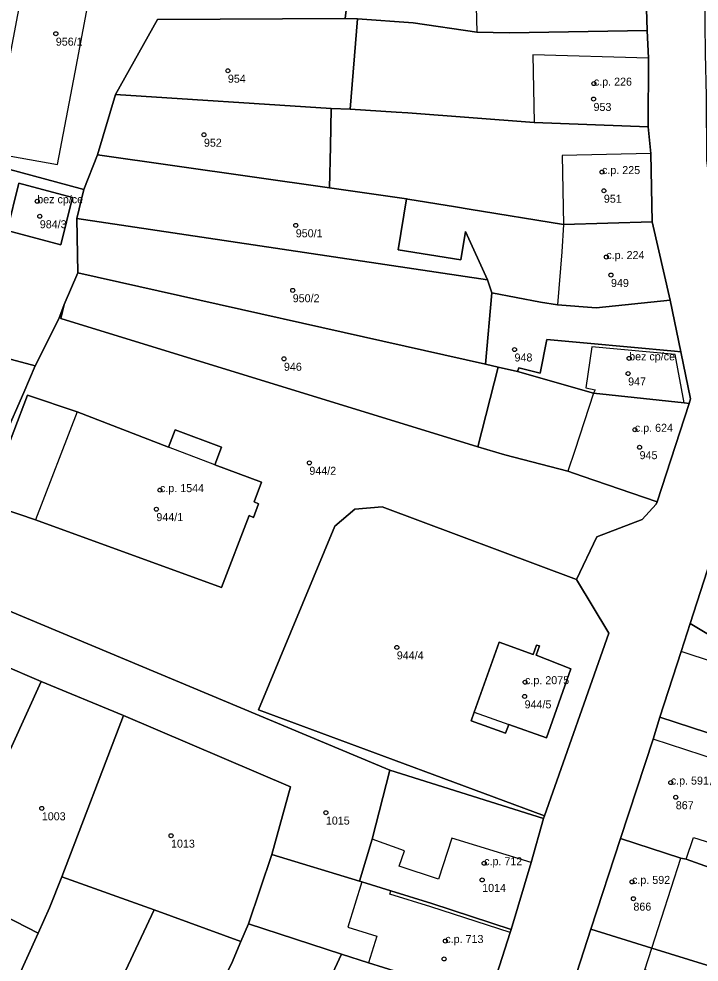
# Model space of a CAD drawing. Extents: x -878211 to -870363, y -1058464 to -1052522.
# Drawn here: x -874902.9 to -874817.9, y -1056517.4 to -1056399.5 of the extents above; entities that cross this region are included whole.
import ezdxf

# ---------------------------------------------------------------- set-up
doc = ezdxf.new("R2010")
doc.units = 0
for name, color, linetype in [('Vrstva 50', 7, 'Continuous'), ('Vrstva 51', 7, 'Continuous'), ('Vrstva 52', 7, 'Continuous')]:
    doc.layers.add(name, color=color, linetype=linetype)

msp = doc.modelspace()

# ---------------------------------------------------------------- linework, layer by layer
at = {"layer": 'Vrstva 50'}
for centre in [(-874898.26, -1056401.36994), (-874876.77, -1056405.99994), (-874831.06, -1056407.60994), (-874831.1, -1056409.52994), (-874879.76, -1056413.99994), (-874830.04, -1056418.65994), (-874829.81, -1056420.99994), (-874900.58, -1056422.30994), (-874900.26, -1056424.18994), (-874868.29, -1056425.31994), (-874829.5, -1056429.27994), (-874828.92, -1056431.52994), (-874868.67, -1056433.43994), (-874840.97, -1056440.83994), (-874869.77, -1056441.99994), (-874826.65, -1056441.93994), (-874826.78, -1056443.83994), (-874825.94, -1056450.86994), (-874825.35, -1056453.04994), (-874866.59, -1056454.99994), (-874885.25, -1056458.40994), (-874885.7, -1056460.78994), (-874855.67, -1056478.06994), (-874839.65, -1056482.40994), (-874839.71, -1056484.18994), (-874821.45, -1056494.95994), (-874820.83, -1056496.79994), (-874900.01, -1056498.17994), (-874864.53, -1056498.71994), (-874883.87, -1056501.59994), (-874844.76, -1056505.03994), (-874845.01, -1056507.12994), (-874826.29, -1056507.36994), (-874826.12, -1056509.46994), (-874849.61, -1056514.75994), (-874849.76, -1056516.99994)]:
    msp.add_circle(centre, 0.25, dxfattribs=at)
at = {"layer": 'Vrstva 51'}
for points in [[(-874923.91, -1056412.98), (-874894.75, -1056420.85), (-874893.04, -1056416.51), (-874890.82, -1056408.96), (-874885.57, -1056399.58), (-874862.13, -1056399.47), (-874861.41, -1056393.71), (-874850.27, -1056392.72), (-874850.58, -1056385.39), (-874853.91, -1056385.5), (-874889.34, -1056382.25), (-874889.5, -1056381.99), (-874894.83, -1056381.48), (-874894.82, -1056381.67), (-874905.74, -1056380.82), (-874918.12, -1056382.02), (-874920.55, -1056383.05), (-874924.5, -1056401.21)], [(-874862.13, -1056399.47), (-874860.57, -1056399.52), (-874853.61, -1056399.99), (-874845.68, -1056401.18), (-874841.61, -1056401.26), (-874824.39, -1056400.97), (-874824.63, -1056394.12), (-874824.76, -1056391.85), (-874850.27, -1056392.72), (-874861.41, -1056393.71)], [(-874862.13, -1056399.47), (-874885.57, -1056399.58), (-874890.82, -1056408.96), (-874863.85, -1056410.72), (-874861.51, -1056410.81), (-874860.57, -1056399.52)], [(-874824.39, -1056400.97), (-874841.61, -1056401.26), (-874845.68, -1056401.18), (-874853.61, -1056399.99), (-874860.57, -1056399.52), (-874861.51, -1056410.81), (-874855.77, -1056411.19), (-874854.3, -1056411.26), (-874838.5, -1056412.46), (-874824.27, -1056413.02), (-874824.24, -1056404.41)], [(-874863.85, -1056410.72), (-874890.82, -1056408.96), (-874893.04, -1056416.51), (-874864.08, -1056420.64), (-874863.96, -1056415.48)], [(-874855.77, -1056411.19), (-874861.51, -1056410.81), (-874863.85, -1056410.72), (-874863.96, -1056415.48), (-874864.08, -1056420.64), (-874854.48, -1056422.01), (-874854.28, -1056422.04), (-874848.36, -1056423.02), (-874846.63, -1056423.3), (-874834.84, -1056425.2), (-874823.79, -1056424.87), (-874823.94, -1056416.32), (-874824.27, -1056413.02), (-874838.5, -1056412.46), (-874854.3, -1056411.26)], [(-874900.82, -1056442.88), (-874897.87, -1056436.98), (-874897.22, -1056435.2), (-874895.51, -1056431.25), (-874895.62, -1056424.45), (-874894.75, -1056420.85), (-874923.91, -1056412.98), (-874927.21, -1056413.07), (-874929.49, -1056422.89), (-874932.5, -1056434.41)], [(-874894.75, -1056420.85), (-874895.62, -1056424.45), (-874844.34, -1056432.12), (-874847.09, -1056426.08), (-874847.67, -1056429.64), (-874855.52, -1056428.37), (-874854.48, -1056422.01), (-874864.08, -1056420.64), (-874893.04, -1056416.51)], [(-874897.65, -1056427.77), (-874904.34, -1056425.96), (-874902.86, -1056420.03), (-874896.16, -1056421.83)], [(-874897.65, -1056427.77), (-874896.16, -1056421.83), (-874902.86, -1056420.03), (-874904.34, -1056425.96)], [(-874855.52, -1056428.37), (-874847.67, -1056429.64), (-874847.09, -1056426.08), (-874844.34, -1056432.12), (-874843.81, -1056433.76), (-874837.74, -1056434.93), (-874835.59, -1056435.25), (-874830.79, -1056435.64), (-874821.53, -1056434.67), (-874823.79, -1056424.87), (-874834.84, -1056425.2), (-874846.63, -1056423.3), (-874848.36, -1056423.02), (-874854.28, -1056422.04), (-874854.48, -1056422.01)], [(-874895.62, -1056424.45), (-874895.51, -1056431.25), (-874844.61, -1056442.68), (-874843.81, -1056433.76), (-874844.34, -1056432.12)], [(-874953.97, -1056437.61), (-874934.97, -1056442.94), (-874904.61, -1056451.62), (-874902.27, -1056446.22), (-874900.82, -1056442.88), (-874932.5, -1056434.41), (-874953.65, -1056428.41), (-874955.52, -1056427.88), (-874956.42, -1056431.54), (-874953.27, -1056432.5), (-874953.77, -1056434.39), (-874954.58, -1056437.43)], [(-874895.51, -1056431.25), (-874897.22, -1056435.2), (-874897.63, -1056436.94), (-874845.55, -1056452.98), (-874843.03, -1056443.04), (-874844.61, -1056442.68)], [(-874821, -1056441.05), (-874820.19, -1056441.13), (-874821.53, -1056434.67), (-874830.79, -1056435.64), (-874835.59, -1056435.25), (-874837.74, -1056434.93), (-874843.81, -1056433.76), (-874844.61, -1056442.68), (-874843.03, -1056443.04), (-874840.6, -1056443.58), (-874840.43, -1056443.11), (-874837.76, -1056443.81), (-874836.92, -1056439.58), (-874831.88, -1056440.03)], [(-874819.17, -1056447.58), (-874818.99, -1056447.01), (-874820.19, -1056441.13), (-874821, -1056441.05), (-874831.88, -1056440.03), (-874836.92, -1056439.58), (-874837.76, -1056443.81), (-874840.43, -1056443.11), (-874840.6, -1056443.58), (-874831.09, -1056446.31), (-874819.77, -1056447.51)], [(-874840.6, -1056443.58), (-874843.03, -1056443.04), (-874845.55, -1056452.98), (-874842.2, -1056454.01), (-874834.32, -1056456.02), (-874832.51, -1056456.65), (-874823.17, -1056459.88), (-874819.17, -1056447.58), (-874819.77, -1056447.51), (-874831.09, -1056446.31)], [(-874895.6, -1056448.63), (-874901.79, -1056446.55), (-874906.96, -1056460.04), (-874900.78, -1056462.13), (-874877.55, -1056470.59), (-874874.12, -1056461.57), (-874873.57, -1056461.82), (-874872.94, -1056460.12), (-874873.5, -1056459.87), (-874872.57, -1056457.43), (-874878.38, -1056455.25), (-874877.57, -1056453.04), (-874883.36, -1056450.87), (-874884.17, -1056453.03)], [(-874895.6, -1056448.63), (-874884.17, -1056453.03), (-874883.36, -1056450.87), (-874877.57, -1056453.04), (-874878.38, -1056455.25), (-874872.57, -1056457.43), (-874873.5, -1056459.87), (-874872.94, -1056460.12), (-874873.57, -1056461.82), (-874874.12, -1056461.57), (-874877.55, -1056470.59), (-874900.78, -1056462.13), (-874906.96, -1056460.04), (-874901.79, -1056446.55)], [(-874804.76, -1056460.13), (-874811.44, -1056456.7), (-874813.36, -1056457.56), (-874816.03, -1056465.77), (-874819.04, -1056475.08), (-874814.33, -1056477.92), (-874808.9, -1056468.02)], [(-874837.24, -1056499.11), (-874829.18, -1056476.29), (-874833.23, -1056469.59), (-874857.5, -1056460.5), (-874860.9, -1056460.79), (-874863.41, -1056462.9), (-874872.96, -1056485.88), (-874856.09, -1056492.13)], [(-874856.56, -1056493.39), (-874912.43, -1056470.04), (-874915.23, -1056475.84), (-874900.11, -1056482.31), (-874889.81, -1056486.59), (-874868.93, -1056495.49), (-874871.28, -1056503.95), (-874860.34, -1056507.29), (-874858.75, -1056502.04)], [(-874814.33, -1056477.92), (-874819.04, -1056475.08), (-874820.16, -1056478.57), (-874822.8, -1056486.77), (-874812.99, -1056489.97), (-874809.77, -1056492.4), (-874806.4, -1056485.31), (-874808.66, -1056483.84), (-874807.41, -1056482.09)], [(-874915.23, -1056475.84), (-874916.64, -1056479.02), (-874920.02, -1056486.22), (-874914.82, -1056488.29), (-874919.17, -1056498.18), (-874909.31, -1056502.51), (-874900.11, -1056482.31)], [(-874841.69, -1056487.68), (-874836.99, -1056489.35), (-874833.93, -1056480.76), (-874838.27, -1056479.05), (-874837.86, -1056477.88), (-874838.24, -1056477.8), (-874838.65, -1056478.93), (-874842.89, -1056477.39), (-874846.02, -1056486.14), (-874846.4, -1056487.23), (-874842.08, -1056488.77)], [(-874841.69, -1056487.68), (-874842.08, -1056488.77), (-874846.4, -1056487.23), (-874846.02, -1056486.14), (-874842.89, -1056477.39), (-874838.65, -1056478.93), (-874838.24, -1056477.8), (-874837.86, -1056477.88), (-874838.27, -1056479.05), (-874833.93, -1056480.76), (-874836.99, -1056489.35)], [(-874897.52, -1056506.72), (-874889.81, -1056486.59), (-874900.11, -1056482.31), (-874909.31, -1056502.51), (-874911.83, -1056507.96), (-874900.48, -1056513.79), (-874899.06, -1056510.59)], [(-874889.81, -1056486.59), (-874897.52, -1056506.72), (-874885.99, -1056510.84), (-874875.15, -1056514.8), (-874874.21, -1056512.61), (-874871.28, -1056503.95), (-874868.93, -1056495.49)], [(-874804.23, -1056495.11), (-874808.2, -1056493.13), (-874809.77, -1056492.4), (-874812.99, -1056489.97), (-874822.8, -1056486.77), (-874823.66, -1056489.55), (-874827.73, -1056501.96), (-874820.2, -1056504.39), (-874819.53, -1056504.54), (-874808.2, -1056508.58), (-874806.96, -1056503.19), (-874806.13, -1056500.61), (-874805.59, -1056499.13)], [(-874856.56, -1056493.39), (-874858.75, -1056502.04), (-874860.34, -1056507.29), (-874860.05, -1056507.38), (-874856.42, -1056508.49), (-874851.3, -1056510.05), (-874841.4, -1056513.31), (-874838.89, -1056504.95), (-874837.33, -1056499.44)], [(-874820.2, -1056504.39), (-874827.73, -1056501.96), (-874831.43, -1056513.29), (-874823.81, -1056515.64), (-874816.96, -1056517.78), (-874810.84, -1056519.83), (-874809.78, -1056515.36), (-874808.2, -1056508.58), (-874819.53, -1056504.54)], [(-874851.3, -1056510.05), (-874856.42, -1056508.49), (-874860.05, -1056507.38), (-874860.34, -1056507.29), (-874871.28, -1056503.95), (-874874.21, -1056512.61), (-874862.56, -1056516.4), (-874859.19, -1056517.5), (-874844.22, -1056522.17), (-874841.52, -1056513.7), (-874841.4, -1056513.31)], [(-874885.99, -1056510.84), (-874897.52, -1056506.72), (-874899.06, -1056510.59), (-874900.48, -1056513.79), (-874903.07, -1056519.58), (-874903.57, -1056520.67), (-874907.13, -1056527.72), (-874896.18, -1056532.77), (-874892.88, -1056525.66), (-874891.51, -1056522.63)], [(-874911.83, -1056507.96), (-874914.59, -1056513.94), (-874918.59, -1056522.44), (-874907.13, -1056527.72), (-874903.57, -1056520.67), (-874903.07, -1056519.58), (-874900.48, -1056513.79)], [(-874885.99, -1056510.84), (-874891.51, -1056522.63), (-874892.88, -1056525.66), (-874896.18, -1056532.77), (-874885.77, -1056537.61), (-874883.2, -1056531.88), (-874882.95, -1056531.34), (-874881.51, -1056528.25), (-874878.63, -1056522.09), (-874876.3, -1056517.59), (-874875.15, -1056514.8)], [(-874862.56, -1056516.4), (-874874.21, -1056512.61), (-874875.15, -1056514.8), (-874876.3, -1056517.59), (-874878.63, -1056522.09), (-874867.02, -1056525.97)], [(-874810.84, -1056519.83), (-874816.96, -1056517.78), (-874823.81, -1056515.64), (-874831.43, -1056513.29), (-874835.36, -1056525.38), (-874825.4, -1056528.66), (-874823.55, -1056529.23), (-874815.62, -1056531.65), (-874814.29, -1056532.05)], [(-874859.19, -1056517.5), (-874862.56, -1056516.4), (-874867.02, -1056525.97), (-874858.46, -1056528.12), (-874856.71, -1056528.74), (-874854.07, -1056529.68), (-874853.92, -1056529.2), (-874847.16, -1056531.42), (-874845.17, -1056525.2), (-874844.22, -1056522.17)]]:
    msp.add_lwpolyline(points, close=True, dxfattribs=at)
for points in [[(-874835.36, -1056525.38), (-874831.43, -1056513.29), (-874827.73, -1056501.96), (-874823.66, -1056489.55), (-874822.8, -1056486.77), (-874820.16, -1056478.57), (-874819.04, -1056475.08), (-874816.03, -1056465.77), (-874813.36, -1056457.56), (-874811.44, -1056456.7), (-874813.86, -1056445.18), (-874814.3, -1056442.72), (-874814.29, -1056440.32), (-874815.43, -1056429.91), (-874816.93, -1056417.19), (-874817.01, -1056409.18), (-874817.1, -1056403.84), (-874817.16, -1056400.09), (-874817.14, -1056390.64)], [(-874824.63, -1056394.12), (-874824.39, -1056400.97), (-874824.24, -1056404.41), (-874824.27, -1056413.02), (-874823.94, -1056416.32), (-874823.79, -1056424.87), (-874821.53, -1056434.67), (-874820.19, -1056441.13), (-874818.99, -1056447.01), (-874819.17, -1056447.58), (-874823.17, -1056459.88), (-874823.27, -1056460.17), (-874825.04, -1056462.06), (-874830.7, -1056464.26), (-874833.23, -1056469.59), (-874829.18, -1056476.29), (-874837.24, -1056499.11), (-874837.33, -1056499.44), (-874838.89, -1056504.95), (-874841.4, -1056513.31), (-874841.52, -1056513.7), (-874844.22, -1056522.17)], [(-874912.43, -1056470.04), (-874856.56, -1056493.39), (-874837.33, -1056499.44), (-874837.24, -1056499.11), (-874856.09, -1056492.13), (-874872.96, -1056485.88), (-874863.41, -1056462.9), (-874860.9, -1056460.79), (-874857.5, -1056460.5), (-874833.23, -1056469.59), (-874830.7, -1056464.26), (-874825.04, -1056462.06), (-874823.27, -1056460.17), (-874823.17, -1056459.88), (-874832.51, -1056456.65), (-874834.32, -1056456.02), (-874842.2, -1056454.01), (-874845.55, -1056452.98), (-874897.63, -1056436.94), (-874897.22, -1056435.2), (-874897.87, -1056436.98), (-874900.82, -1056442.88), (-874902.27, -1056446.22), (-874904.61, -1056451.62)]]:
    msp.add_lwpolyline(points, dxfattribs=at)
at = {"layer": 'Vrstva 52'}
for points in [[(-874919.29, -1056391.92), (-874919.61, -1056394.29), (-874915.96, -1056394.74), (-874915.61, -1056392.19), (-874905.02, -1056392.98), (-874901.98, -1056393.2), (-874904.11, -1056404.76), (-874906.24, -1056416.24), (-874898.07, -1056417.7), (-874895.86, -1056406.18), (-874894.55, -1056399.35), (-874892.45, -1056387.93), (-874896.72, -1056387.12), (-874896.52, -1056385.93), (-874897.95, -1056385.7), (-874898.12, -1056386.86), (-874899.99, -1056386.5), (-874899.81, -1056384.72), (-874918.34, -1056382.71)], [(-874845.83, -1056394.73), (-874845.68, -1056401.18), (-874841.61, -1056401.26), (-874824.39, -1056400.97), (-874824.63, -1056394.12)], [(-874824.24, -1056404.41), (-874838.68, -1056403.99), (-874838.5, -1056412.46), (-874824.27, -1056413.02)], [(-874835.01, -1056416.58), (-874834.84, -1056425.2), (-874823.79, -1056424.87), (-874823.94, -1056416.32)], [(-874904.34, -1056425.96), (-874897.65, -1056427.77), (-874896.16, -1056421.83), (-874902.86, -1056420.03)], [(-874835.06, -1056428.63), (-874835.59, -1056435.25), (-874830.79, -1056435.64), (-874821.53, -1056434.67), (-874823.79, -1056424.87), (-874834.84, -1056425.2)], [(-874831.3, -1056440.49), (-874832.06, -1056445.63), (-874830.89, -1056445.86), (-874831.09, -1056446.31), (-874819.77, -1056447.51), (-874820.91, -1056441.44)], [(-874823.17, -1056459.88), (-874819.17, -1056447.58), (-874819.77, -1056447.51), (-874831.09, -1056446.31), (-874833.43, -1056453.45), (-874834.32, -1056456.02), (-874832.51, -1056456.65)], [(-874900.78, -1056462.13), (-874877.55, -1056470.59), (-874874.12, -1056461.57), (-874873.57, -1056461.82), (-874872.94, -1056460.12), (-874873.5, -1056459.87), (-874872.57, -1056457.43), (-874878.38, -1056455.25), (-874884.17, -1056453.03), (-874895.6, -1056448.63)], [(-874846.02, -1056486.14), (-874841.69, -1056487.68), (-874836.99, -1056489.35), (-874833.93, -1056480.76), (-874838.27, -1056479.05), (-874837.86, -1056477.88), (-874838.24, -1056477.8), (-874838.65, -1056478.93), (-874842.89, -1056477.39)], [(-874822.8, -1056486.77), (-874812.99, -1056489.97), (-874811.08, -1056484.13), (-874812.88, -1056483.52), (-874811.97, -1056481.3), (-874820.16, -1056478.57)], [(-874818.62, -1056501.84), (-874815.72, -1056502.73), (-874814.12, -1056498.1), (-874813.63, -1056498.21), (-874813.12, -1056496.33), (-874816.47, -1056495.25), (-874815.51, -1056492.2), (-874823.66, -1056489.55), (-874827.73, -1056501.96), (-874820.2, -1056504.39), (-874819.53, -1056504.54)], [(-874860.34, -1056507.29), (-874860.05, -1056507.38), (-874856.42, -1056508.49), (-874851.3, -1056510.05), (-874841.4, -1056513.31), (-874838.89, -1056504.95), (-874848.79, -1056501.9), (-874850.48, -1056507.01), (-874855.36, -1056505.4), (-874854.72, -1056503.48), (-874858.75, -1056502.04)], [(-874831.43, -1056513.29), (-874823.81, -1056515.64), (-874820.2, -1056504.39), (-874827.73, -1056501.96)], [(-874861.78, -1056513.02), (-874858.15, -1056514.16), (-874859.19, -1056517.5), (-874844.22, -1056522.17), (-874841.52, -1056513.7), (-874851.43, -1056510.47), (-874856.54, -1056508.91), (-874856.42, -1056508.49), (-874860.05, -1056507.38)], [(-874835.36, -1056525.38), (-874825.4, -1056528.66), (-874823.55, -1056529.23), (-874822.41, -1056525.8), (-874822.98, -1056525.61), (-874821.85, -1056522.19), (-874820.51, -1056522.55), (-874819.65, -1056519.95), (-874824.69, -1056518.38), (-874823.81, -1056515.64), (-874831.43, -1056513.29)]]:
    msp.add_lwpolyline(points, close=True, dxfattribs=at)

# ---------------------------------------------------------------- texts
at = {"layer": 'Vrstva 50'}
for s, p in [('956/1', (-874898.26, -1056402.859)), ('954', (-874876.77, -1056407.489)), ('c.p. 226', (-874831.06, -1056407.86)), ('953', (-874831.1, -1056411.019)), ('952', (-874879.76, -1056415.489)), ('c.p. 225', (-874830.04, -1056418.909)), ('bez cp/ce', (-874900.58, -1056422.56)), ('951', (-874829.81, -1056422.489)), ('984/3', (-874900.26, -1056425.679)), ('950/1', (-874868.29, -1056426.809)), ('c.p. 224', (-874829.5, -1056429.53)), ('949', (-874828.92, -1056433.019)), ('950/2', (-874868.67, -1056434.929)), ('948', (-874840.97, -1056442.329)), ('bez cp/ce', (-874826.65, -1056442.19)), ('946', (-874869.77, -1056443.489)), ('947', (-874826.78, -1056445.329)), ('c.p. 624', (-874825.94, -1056451.12)), ('945', (-874825.35, -1056454.539)), ('944/2', (-874866.59, -1056456.489)), ('c.p. 1544', (-874885.25, -1056458.659)), ('944/1', (-874885.7, -1056462.279)), ('944/4', (-874855.67, -1056479.559)), ('c.p. 2075', (-874839.65, -1056482.659)), ('944/5', (-874839.71, -1056485.679)), ('c.p. 591', (-874821.45, -1056495.21)), ('867', (-874820.83, -1056498.289)), ('1003', (-874900.01, -1056499.669)), ('1015', (-874864.53, -1056500.209)), ('1013', (-874883.87, -1056503.089)), ('c.p. 712', (-874844.76, -1056505.29)), ('c.p. 592', (-874826.29, -1056507.62)), ('1014', (-874845.01, -1056508.619)), ('866', (-874826.12, -1056510.959)), ('c.p. 713', (-874849.61, -1056515.01))]:
    msp.add_text(s, height=0.999996, dxfattribs=at).set_placement(p)

doc.saveas('drawing.dxf')
